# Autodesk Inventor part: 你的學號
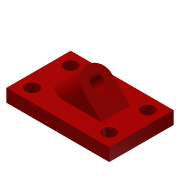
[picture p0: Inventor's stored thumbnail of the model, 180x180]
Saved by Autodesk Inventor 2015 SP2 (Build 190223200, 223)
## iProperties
Created: 2019-07
Part Number: 你的學號
Material: 一般
Document SubType Name: Modeling
Density: 1 g/cm^3
Appearance: Smooth - Red
Author: 你的姓名
Title: 輔助投影視圖
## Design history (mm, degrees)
sketch "草圖1"
  geometry: L1 (-80, -50)-(80, -50); L2 (80, -50)-(80, 50); L3 (80, 50)-(-80, 50); L4 (-80, 50)-(-80, -50); L5 (-80, -50)-(80, 50); L6 (80, -50)-(-80, 50); 1 further point
  constraints: 12 end point, 2 midpoint, 2 parallel, 1 horizontal, 1 perpendicular
  dimensions: "d0" = 160 distance of L2.end L3.end; "d1" = 100 distance of L3.end L1.start
extrude "擠出1" new body sketch "草圖1" stored distance "d2" = 20; taper "d3" = 0 deg
node "工作平面2"
  node "工作軸線1"
sketch "草圖2"
  geometry: L1 (-70, 0)-(70, 0) reference; L2 (-22.5, 40)-(22.5, 40); L3 (22.5, 40)-(22.5, 0); L4 (22.5, 0)-(-22.5, 0); L5 (-22.5, 0)-(-22.5, 40); L6 (-22.5, 40)-(22.5, 0); L7 (22.5, 40)-(-22.5, 0); L8 (-50, 84.853)-(-50, -28.284) reference; L9 (-50, -28.284)-(50, -28.284) reference; L10 (50, -28.284)-(50, 84.853) reference; L11 (50, 84.853)-(-50, 84.853) reference; L12 (-50, 0)-(50, 0); L13 (50, -28.284)-(50, 84.853) reference; 4 further points
  constraints: 14 end point, 5 midpoint, 4 point on line, 2 parallel, 1 horizontal, 1 horizontal alignment, 1 perpendicular, 2 other
  dimensions: "d6" = 40 distance of L2.end L3.end; "d7" = 45 distance of L2.start L2.end
extrude "擠出2" join sketch "草圖2" stored distance "d8" = 20; taper "d9" = 0 deg
sketch "草圖3"
  geometry: C1 r 10 at (-40, 0); A1 r 22.5 centre (-40, 0) between (-40, 22.5) and (-40, -22.5) reference; 1 further point
  constraints: 1 centre point, 1 coincident
  dimensions: "d10" = 20 diameter of C1
extrude "擠出3" cut sketch "草圖3" stored distance "d11" = 20; taper "d12" = 0 deg
sketch "草圖4"
  geometry: L1 (-60, -30)-(60, -30); L2 (60, -30)-(60, 30); L3 (60, 30)-(-60, 30); L4 (-60, 30)-(-60, -30); L5 (-60, -30)-(60, 30); L6 (60, -30)-(-60, 30); C1 r 10 at (-60, 30); C2 r 10 at (60, 30); C3 r 10 at (60, -30); C4 r 10 at (-60, -30); 3 further points
  constraints: 12 end point, 5 coincident, 4 centre point, 3 equal radius, 3 midpoint, 2 parallel, 1 horizontal, 1 perpendicular
  dimensions: "d13" = 20 diameter of C1; "d14" = 120 distance of L2.end L3.end; "d15" = 60 distance of L3.end L1.start
extrude "擠出4" cut sketch "草圖4" stored distance "d16" = 20; taper "d17" = 0 deg
node "實體1"
node "工作平面1"
node "投影迴路1"
other parameters: "d5" = 45 deg
